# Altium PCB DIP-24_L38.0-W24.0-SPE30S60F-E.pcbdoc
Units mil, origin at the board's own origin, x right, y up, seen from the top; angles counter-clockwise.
Board outline 2020 x 1717.48 mil, 2 copper layers (Top Layer, Bottom Layer), stack 0 mil thick; 1 components, 0 nets, 24 pads, 0 vias.
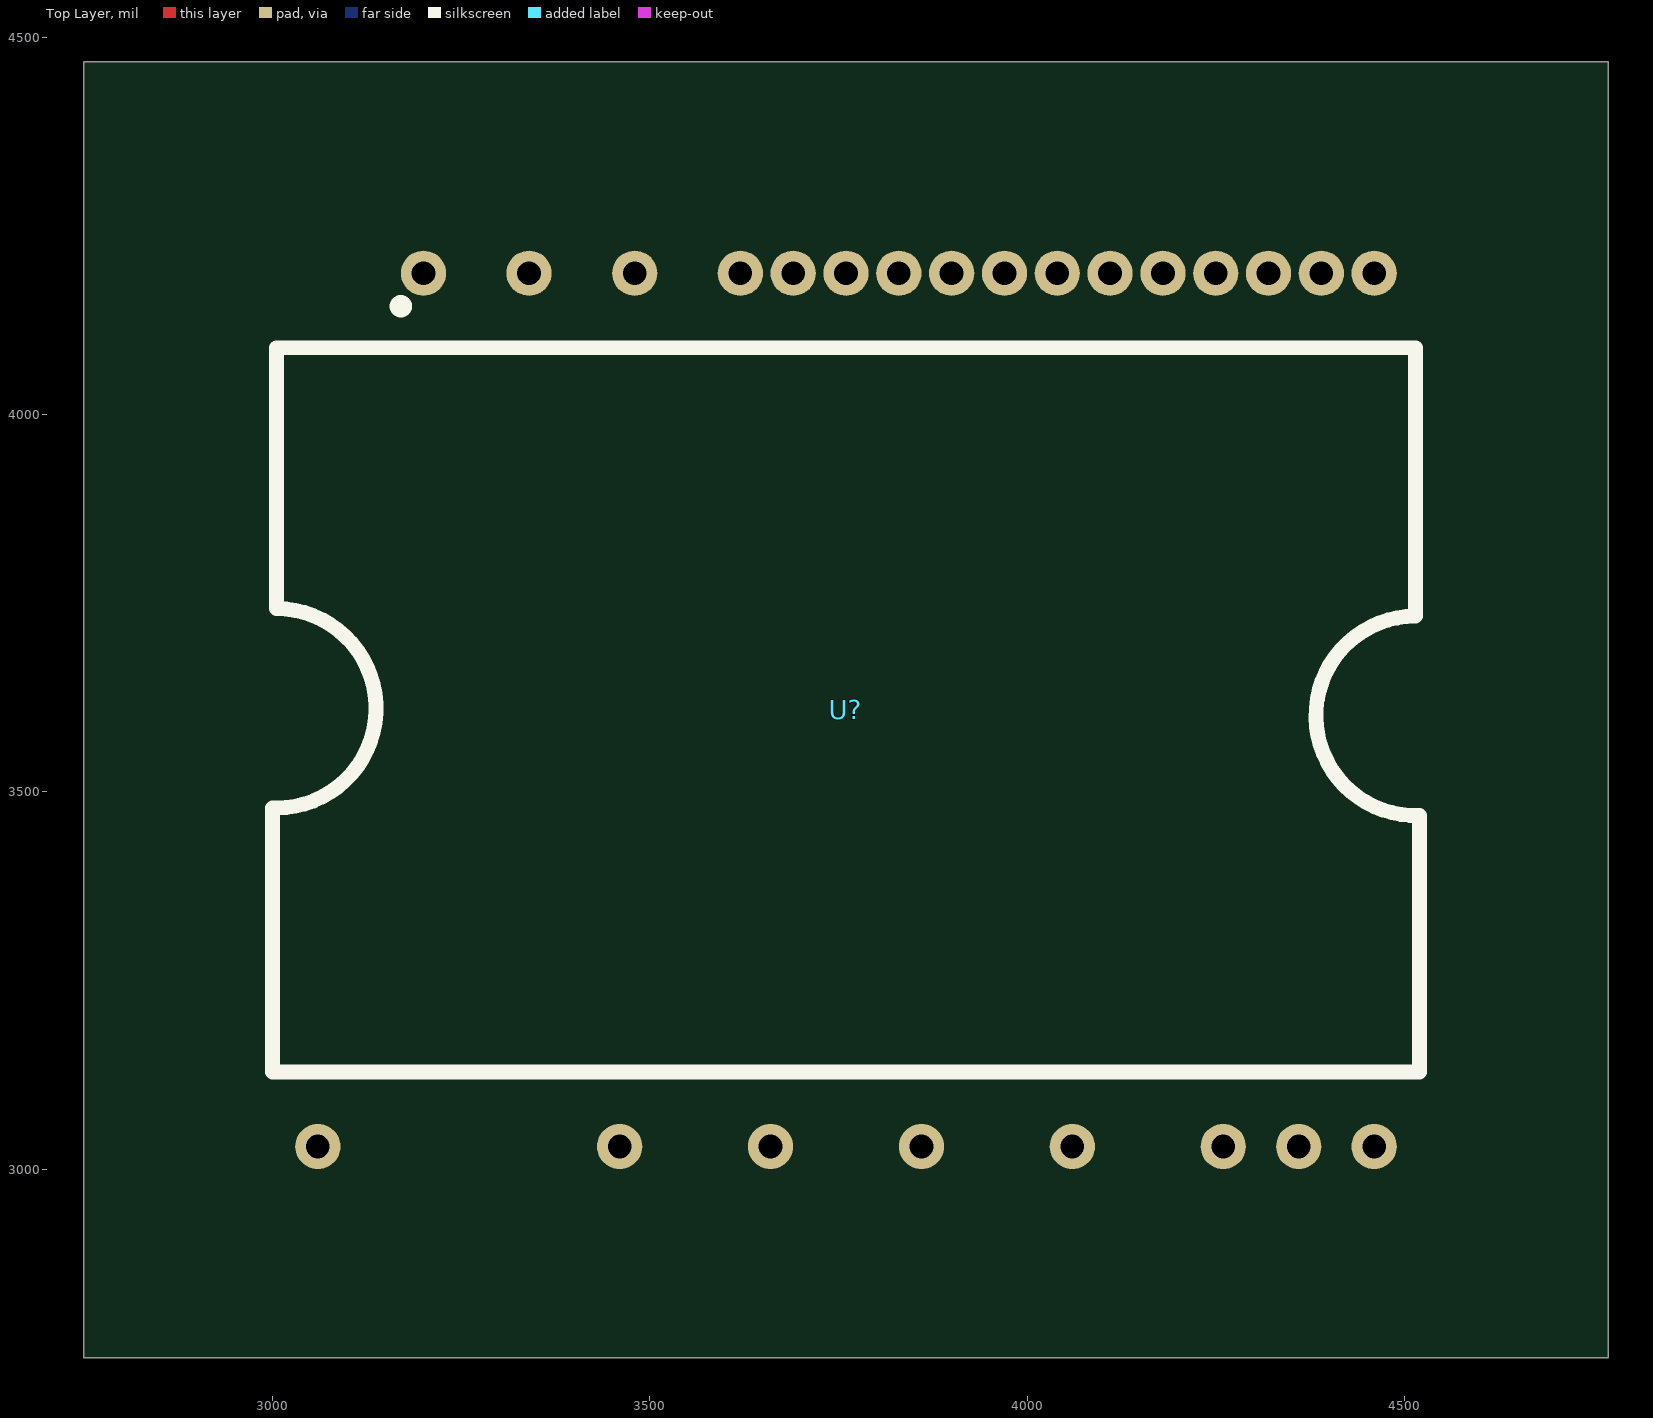
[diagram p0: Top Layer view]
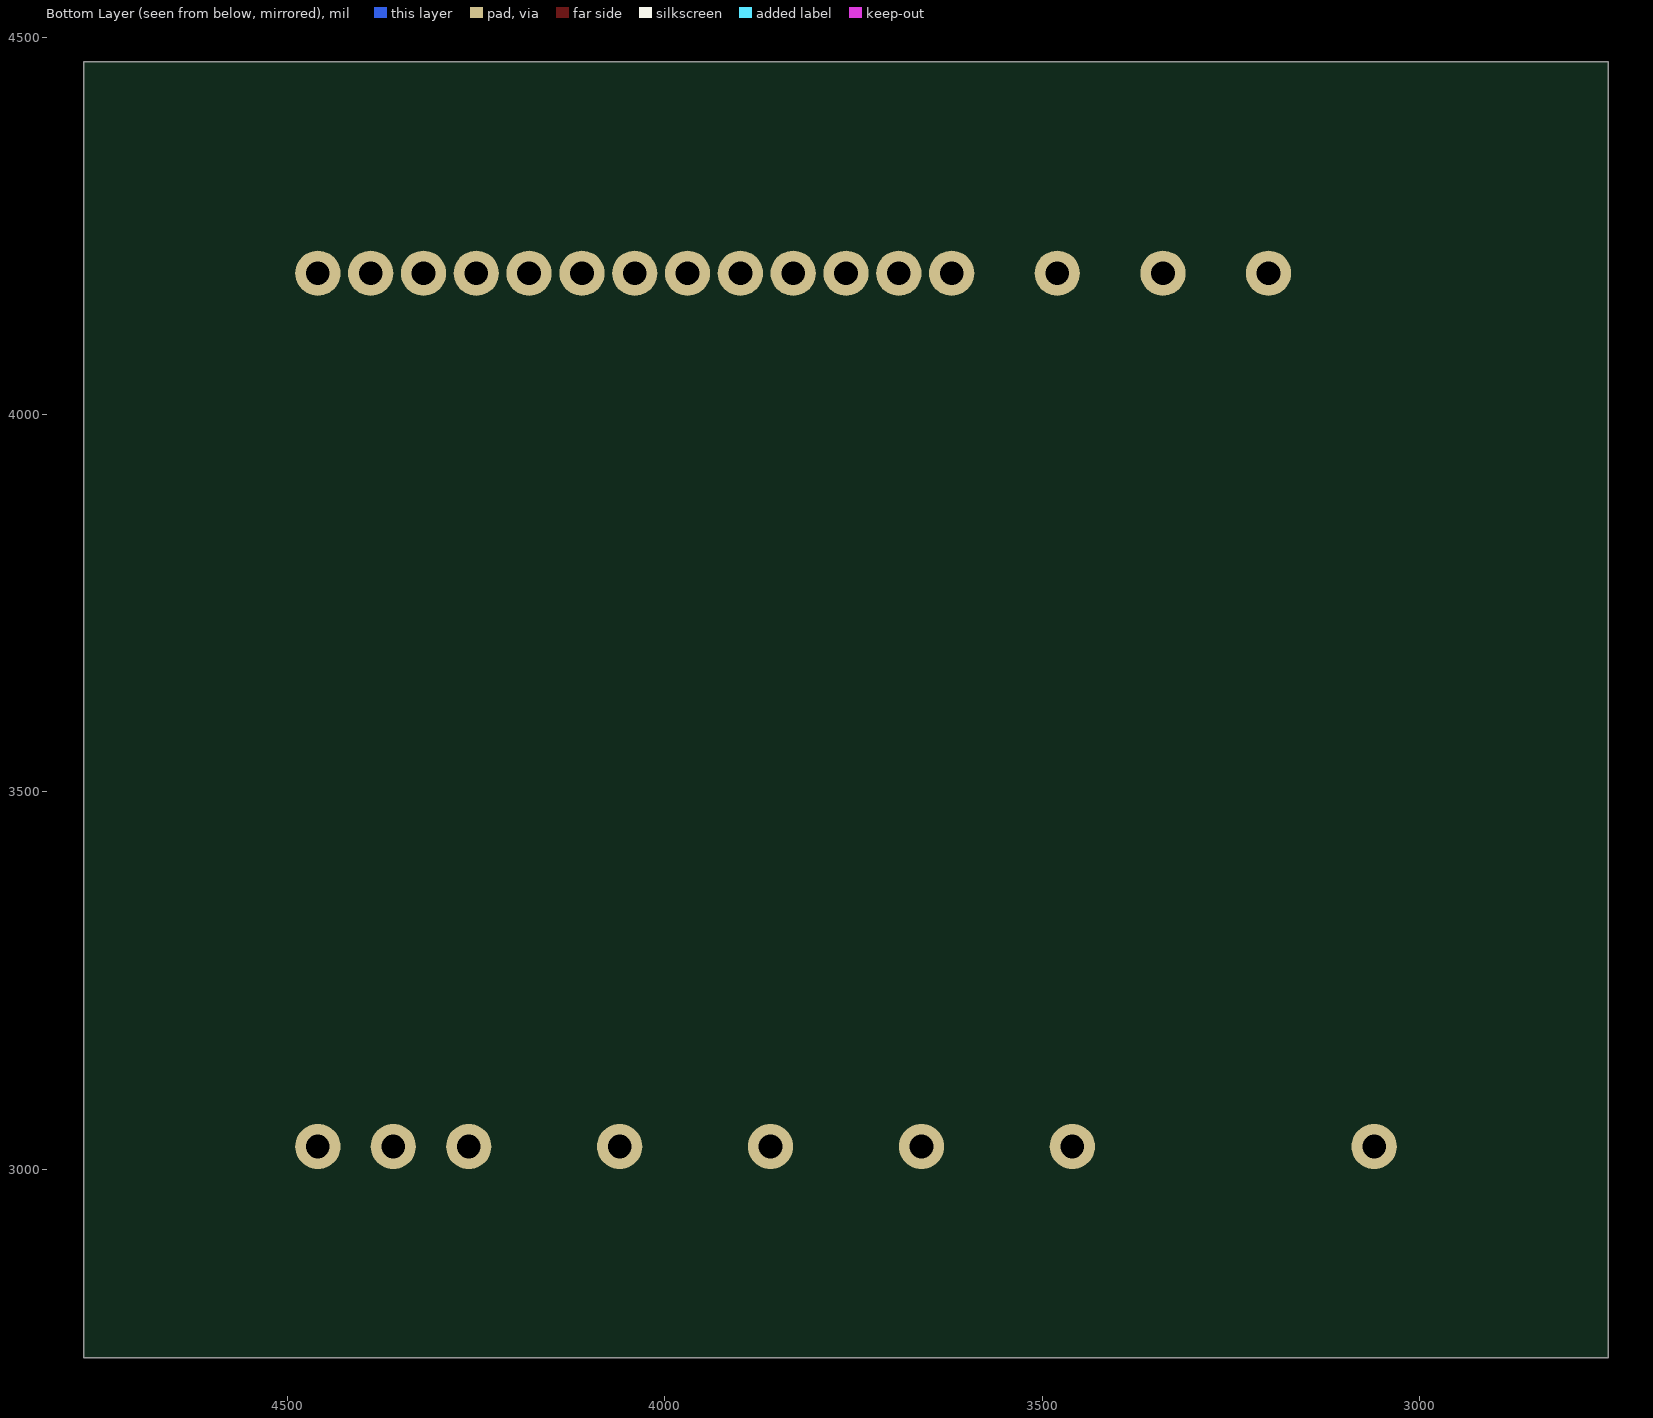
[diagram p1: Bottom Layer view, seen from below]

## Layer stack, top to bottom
Top Layer: signal copper (thickness not stored)
Bottom Layer: signal copper (thickness not stored)

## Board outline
4770,2750 2750,2750 2750,4467.48 4770,4467.48

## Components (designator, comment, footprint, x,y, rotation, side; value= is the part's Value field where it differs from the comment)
U? "" DIP-24_L38.0-W24.0-SPE30S60F-E 3760,3608.74 r0 top

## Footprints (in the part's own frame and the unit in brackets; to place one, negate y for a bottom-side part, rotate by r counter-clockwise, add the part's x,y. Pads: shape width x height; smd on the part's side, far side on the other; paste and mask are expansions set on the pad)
DIP-24_L38.0-W24.0-SPE30S60F-E [mil]
  round 60 hole 31.5 paste+0 mask+2.01: 2(-560,578.74) 3(-420,578.74) 4(-280,578.74) 5(-140,578.74) 6(-70,578.74) 7(0,578.74) 8(70,578.74) 9(140,578.74) 10(210,578.74) 11(280,578.74) 12(350,578.74) 13(420,578.74) 14(490,578.74) 15(559.99,578.74) 16(629.99,578.74) 17(700,578.74) 18(699.99,-578.74) 19(600,-578.74) 20(500,-578.74) 21(300,-578.74) 22(100,-578.74) 23(-100,-578.74) 24(-300,-578.74) 25(-700,-578.74)
  silkscreen extent -760,-480 760,540

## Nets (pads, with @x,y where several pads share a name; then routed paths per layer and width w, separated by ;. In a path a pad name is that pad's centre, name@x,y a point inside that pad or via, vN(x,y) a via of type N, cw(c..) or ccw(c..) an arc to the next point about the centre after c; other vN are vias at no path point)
pads on no net: U?.2 U?.3 U?.4 U?.5 U?.6 U?.7 U?.8 U?.9 U?.10 U?.11 U?.12 U?.13 U?.14 U?.15 U?.16 U?.17 U?.18 U?.19 U?.20 U?.21 U?.22 U?.23 U?.24 U?.25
